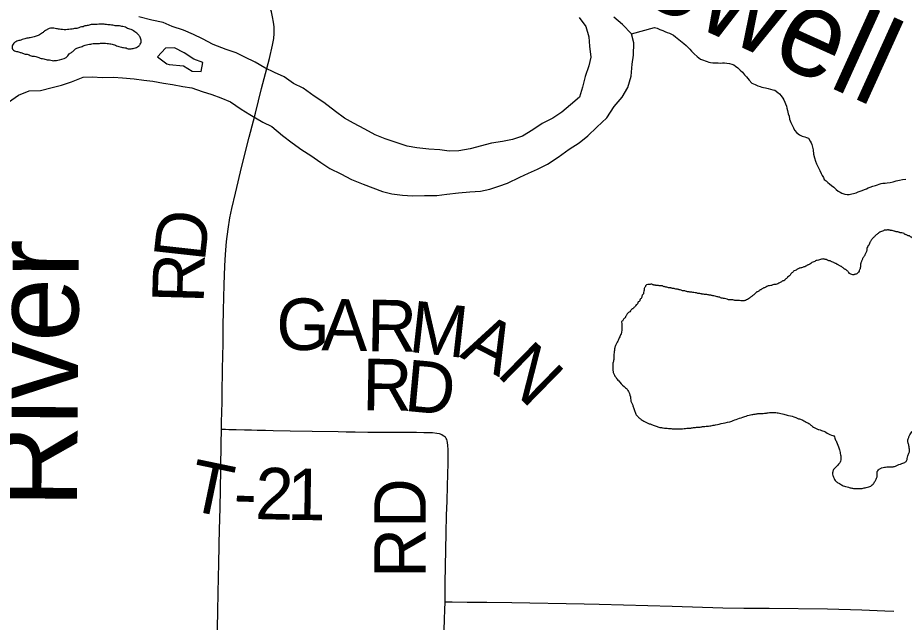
# Model space of a CAD drawing. Extents: x -483 to 680, y 0 to 440.
# Drawn here: x 240.28 to 289.15, y 248.81 to 282.12 of the extents above; entities that cross this region are included whole.
import ezdxf

# ---------------------------------------------------------------- set-up
doc = ezdxf.new("R2010")
doc.units = 0
for name, color, linetype in [('GM_X_County_Road', 7, 'Continuous'), ('GM_X_County_Road_Text', 7, 'Continuous'), ('GM_X_Major_River', 7, 'Continuous'), ('GM_X_Major_River_Text', 7, 'Continuous'), ('GM_X_Minor_Lake', 7, 'Continuous'), ('GM_X_Minor_River', 7, 'Continuous'), ('GM_X_Minor_River_Text', 7, 'Continuous'), ('GM_X_Township_Road', 7, 'Continuous'), ('GM_X_Township_Road_Text', 7, 'Continuous')]:
    doc.layers.add(name, color=color, linetype=linetype)

msp = doc.modelspace()

# ---------------------------------------------------------------- linework, layer by layer
at = {"layer": 'GM_X_County_Road'}
for points in [[(254.152, 279.874), (254.33, 280.605), (254.397, 280.979), (254.412, 281.254), (254.406, 281.623), (254.382, 281.867), (254.328, 282.168), (254.258, 282.434), (254.185, 282.635), (254.06, 282.916), (253.974, 283.098)], [(253.27, 276.434), (253.378, 276.855), (253.723, 278.21), (254.152, 279.874)], [(251.509, 259.452), (251.515, 259.825), (251.54, 260.943), (251.548, 261.378), (251.573, 262.777), (251.594, 264.168), (251.593, 264.415), (251.607, 265.097), (251.628, 265.998), (251.655, 267.396), (251.688, 268.453), (251.726, 269.075), (251.791, 269.789), (251.879, 270.469), (251.978, 271.084), (252.08, 271.604), (252.274, 272.453), (252.637, 273.933), (253.036, 275.53), (253.27, 276.434)], [(251.256, 246.808), (251.299, 249.391), (251.322, 250.452), (251.357, 252.063), (251.377, 252.993), (251.399, 254.016), (251.41, 254.388), (251.451, 256.034), (251.494, 258.613), (251.509, 259.452)]]:
    msp.add_lwpolyline(points, dxfattribs=at)
at = {"layer": 'GM_X_Major_River'}
for points in [[(239.766, 277.473), (240.326, 277.856), (240.901, 278.087), (241.527, 278.108), (242.177, 278.28), (242.692, 278.398), (243.247, 278.592), (243.88, 278.84), (244.373, 278.864), (244.941, 278.83), (245.548, 278.851), (246.059, 278.799), (246.702, 278.744), (247.23, 278.672), (247.722, 278.621), (248.306, 278.51), (248.816, 278.439), (249.382, 278.328), (249.873, 278.258), (250.436, 278.053), (250.981, 277.886), (251.469, 277.702), (252.012, 277.478), (252.589, 277.083), (253.073, 276.785), (253.782, 276.367), (254.287, 276.125), (254.88, 275.635), (255.399, 275.222), (255.938, 274.846), (256.441, 274.529), (256.98, 274.135), (257.483, 273.817), (258.081, 273.516), (258.679, 273.196), (259.317, 272.951), (259.861, 272.746), (260.386, 272.542), (260.894, 272.414), (261.48, 272.341), (262.048, 272.307), (262.693, 272.327), (263.375, 272.327), (263.927, 272.388), (264.573, 272.465), (265.201, 272.523), (265.789, 272.564), (266.304, 272.664), (266.802, 272.84), (267.28, 272.997), (267.953, 273.339), (268.433, 273.554), (268.932, 273.768), (269.49, 274.056), (270.069, 274.439), (270.669, 274.878), (271.229, 275.223), (271.713, 275.608), (272.201, 276.088), (272.746, 276.604), (273.161, 277.219), (273.593, 277.738), (273.911, 278.28), (274.1, 278.901), (274.156, 279.563), (274.227, 280.054), (274.246, 280.737), (274.108, 281.234), (273.61, 281.741), (273.129, 282.153)], [(271.233, 282.129), (271.598, 281.626), (271.753, 281.071), (271.795, 280.558), (271.873, 279.948), (271.764, 279.458), (271.559, 278.876), (271.409, 278.291), (271.243, 277.746), (270.757, 277.323), (270.272, 276.919), (269.769, 276.591), (269.192, 276.284), (268.671, 275.938), (268.111, 275.593), (267.556, 275.4), (267.003, 275.301), (266.394, 275.204), (265.21, 274.895), (264.6, 274.779), (264.069, 274.774), (263.54, 274.846), (262.935, 274.882), (262.273, 274.957), (261.745, 275.047), (261.087, 275.255), (260.524, 275.441), (259.98, 275.665), (259.402, 275.984), (258.785, 276.305), (258.281, 276.585), (257.799, 276.958), (257.149, 277.45), (256.627, 277.787), (256.015, 278.241), (255.472, 278.502), (254.97, 278.858), (254.427, 279.1), (253.904, 279.361), (253.362, 279.661), (252.802, 279.942), (252.315, 280.183), (251.771, 280.369), (251.058, 280.635), (250.46, 280.955), (249.974, 281.196), (249.412, 281.439), (248.792, 281.627), (248.286, 281.85), (247.664, 281.981), (246.949, 282.171)], [(249.414, 279.466), (249.898, 279.168), (250.391, 279.154), (250.48, 279.645), (249.993, 279.829), (249.453, 280.186), (248.911, 280.466), (248.417, 280.442), (247.987, 279.96), (248.488, 279.586), (248.62, 279.545)], [(248.62, 279.545), (249.414, 279.466)]]:
    msp.add_lwpolyline(points, dxfattribs=at)
for points in [[(242.651, 281.47), (242.518, 281.492), (242.405, 281.514), (242.273, 281.536), (242.159, 281.539), (242.007, 281.524), (241.872, 281.452), (241.757, 281.379), (241.64, 281.286), (241.525, 281.213), (241.409, 281.14), (241.18, 281.07), (241.027, 281.036), (240.912, 281.001), (240.779, 280.985), (240.664, 280.95), (240.512, 280.916), (240.397, 280.862), (240.282, 280.846), (240.167, 280.792), (240.052, 280.719), (239.992, 280.606), (239.97, 280.493), (239.986, 280.379), (240.098, 280.3), (240.211, 280.259), (240.324, 280.237), (240.493, 280.176), (240.681, 280.115), (240.908, 280.071), (241.02, 280.011), (241.134, 280.008), (241.266, 279.986), (241.379, 279.945), (241.642, 279.863), (241.775, 279.84), (241.906, 279.799), (242.02, 279.796), (242.171, 279.754), (242.285, 279.752), (242.418, 279.767), (242.57, 279.801), (243.031, 280.018), (243.11, 280.13), (243.245, 280.202), (243.381, 280.332), (243.535, 280.442), (243.65, 280.477), (243.765, 280.512), (243.88, 280.566), (243.995, 280.601), (244.3, 280.669), (244.566, 280.701), (244.718, 280.697), (244.832, 280.713), (245.211, 280.703), (245.476, 280.659), (245.608, 280.617), (245.72, 280.577), (245.852, 280.535), (246.003, 280.494), (246.116, 280.472), (246.248, 280.45), (246.361, 280.409), (246.475, 280.406), (246.703, 280.438), (246.934, 280.546), (247.031, 280.658), (247.072, 280.771), (247.075, 280.884), (247.04, 280.999), (246.949, 281.153), (246.838, 281.27), (246.726, 281.349), (246.464, 281.488), (246.333, 281.529), (246.22, 281.589), (246.07, 281.631), (245.956, 281.653), (245.824, 281.675), (245.653, 281.679), (245.521, 281.702), (245.37, 281.725), (245.237, 281.728), (245.105, 281.75), (244.972, 281.754), (244.745, 281.759), (244.574, 281.745), (244.441, 281.748), (244.213, 281.716), (244.098, 281.681), (243.984, 281.664), (243.885, 281.619)], [(243.885, 281.619), (243.716, 281.595), (243.582, 281.542), (243.468, 281.525), (243.354, 281.509), (243.011, 281.461), (242.651, 281.47)]]:
    msp.add_spline(points, degree=3, dxfattribs=at)
at = {"layer": 'GM_X_Minor_Lake'}
for points in [[(290.913, 269.044), (290.892, 269.058), (290.836, 269.117), (290.78, 269.156), (290.725, 269.214), (290.668, 269.235), (290.296, 269.528), (290.24, 269.568), (290.165, 269.608), (290.11, 269.666), (290.053, 269.686), (289.997, 269.726), (289.922, 269.765), (289.81, 269.844), (289.736, 269.884), (289.679, 269.923), (289.605, 269.963), (289.549, 270.021), (289.493, 270.042), (289.437, 270.1), (289.361, 270.102), (289.305, 270.141), (289.249, 270.161), (289.193, 270.182), (289.137, 270.221), (289.024, 270.262), (288.967, 270.263), (288.892, 270.284), (288.835, 270.304), (288.76, 270.325), (288.703, 270.327), (288.646, 270.347), (288.59, 270.348), (288.477, 270.389), (288.42, 270.391), (288.363, 270.411), (288.306, 270.412), (288.25, 270.433), (288.193, 270.415), (288.079, 270.418), (288.002, 270.382), (287.887, 270.347), (287.714, 270.237), (287.636, 270.182), (287.5, 270.052), (287.442, 269.997), (287.384, 269.941), (287.325, 269.867), (287.285, 269.792), (287.246, 269.736), (287.205, 269.623), (287.166, 269.567), (287.084, 269.341), (287.083, 269.284), (287.062, 269.228), (287.023, 269.172), (286.962, 269.003), (286.923, 268.947), (286.864, 268.872), (286.843, 268.816), (286.804, 268.741), (286.783, 268.684), (286.762, 268.609), (286.742, 268.553), (286.739, 268.439), (286.718, 268.344), (286.716, 268.287), (286.677, 268.231), (286.656, 268.156), (286.577, 268.044), (286.5, 267.989), (286.424, 267.972), (286.367, 267.954), (286.31, 267.956), (286.197, 267.996), (286.085, 268.075), (286.03, 268.152), (285.974, 268.192), (285.918, 268.25), (285.862, 268.27), (285.806, 268.31), (285.75, 268.349)], [(285.75, 268.349), (285.695, 268.407), (285.638, 268.428), (285.563, 268.467), (285.507, 268.507), (285.451, 268.527), (285.395, 268.567), (285.32, 268.587), (285.264, 268.627), (285.151, 268.667), (285.095, 268.707), (285.038, 268.727), (284.982, 268.728), (284.925, 268.749), (284.869, 268.788), (284.812, 268.79), (284.756, 268.81), (284.585, 268.814), (284.356, 268.744), (284.299, 268.745), (284.221, 268.69), (284.107, 268.655), (283.875, 268.509), (283.818, 268.491), (283.76, 268.455), (283.664, 268.4), (283.607, 268.383), (283.53, 268.346), (283.358, 268.313), (283.3, 268.276), (283.243, 268.259), (283.185, 268.203), (283.07, 268.168), (283.031, 268.112), (282.953, 268.057), (282.895, 268.001), (282.816, 267.889), (282.72, 267.835), (282.7, 267.778), (282.622, 267.723), (282.563, 267.649), (282.449, 267.614), (282.314, 267.522), (282.237, 267.486), (282.007, 267.416), (281.951, 267.417), (281.874, 267.381), (281.797, 267.364), (281.511, 267.276), (281.453, 267.239), (281.376, 267.222), (281.319, 267.186), (281.241, 267.131), (281.184, 267.113), (281.126, 267.058), (281.049, 267.022), (280.991, 266.985), (280.913, 266.911), (280.855, 266.855), (280.797, 266.819), (280.739, 266.763), (280.681, 266.727), (280.622, 266.671), (280.507, 266.598), (280.392, 266.544), (280.315, 266.527), (279.974, 266.535), (279.803, 266.54), (279.747, 266.56), (279.538, 266.565), (279.237, 266.648), (279.18, 266.65), (279.066, 266.671), (278.973, 266.712), (278.784, 266.754), (278.652, 266.795), (278.595, 266.797), (278.52, 266.818), (278.35, 266.841), (278.274, 266.862), (278.198, 266.863), (278.085, 266.885), (277.99, 266.888), (277.934, 266.908), (277.82, 266.93), (277.763, 266.931), (277.688, 266.952), (277.556, 266.974), (277.499, 266.976), (277.386, 266.997), (277.329, 266.999), (277.253, 267.02), (277.196, 267.021), (277.14, 267.041), (277.046, 267.063), (276.951, 267.065), (276.894, 267.085)], [(276.894, 267.085), (276.801, 267.126), (276.744, 267.127), (276.687, 267.147), (276.612, 267.168), (276.555, 267.17), (276.461, 267.191), (276.404, 267.192), (276.328, 267.213), (276.272, 267.233), (276.215, 267.235), (276.158, 267.236), (276.064, 267.276), (276.007, 267.278), (275.932, 267.299), (275.875, 267.3), (275.819, 267.339), (275.629, 267.344), (275.573, 267.364), (275.459, 267.367), (275.403, 267.387), (275.346, 267.389), (275.29, 267.409), (275.233, 267.43), (275.176, 267.431), (275.119, 267.413), (275.005, 267.416), (274.889, 267.343), (274.869, 267.287), (274.83, 267.231), (274.809, 267.174), (274.807, 267.098), (274.767, 266.986), (274.765, 266.91), (274.706, 266.835), (274.685, 266.779), (274.684, 266.722), (274.644, 266.647), (274.586, 266.61), (274.565, 266.516), (274.488, 266.461), (274.447, 266.348), (274.37, 266.293), (274.311, 266.199), (274.233, 266.144), (274.213, 266.088), (274.155, 266.07), (274.058, 265.959), (273.98, 265.885), (273.922, 265.848), (273.844, 265.736), (273.785, 265.662), (273.764, 265.586), (273.687, 265.531), (273.647, 265.475), (273.607, 265.401), (273.568, 265.388)], [(273.568, 265.388), (273.552, 264.769), (273.51, 264.637), (273.41, 264.431), (273.329, 264.243), (273.249, 264.093), (273.187, 263.924), (273.163, 263.735), (273.135, 263.412), (273.132, 263.279), (273.089, 263.09), (273.081, 262.768), (273.095, 262.615), (273.149, 262.462), (273.258, 262.288), (273.405, 262.113), (273.701, 261.801), (273.869, 261.644), (273.959, 261.49), (274.065, 261.145), (274.079, 260.992), (274.152, 260.838), (274.205, 260.685), (274.275, 260.474), (274.346, 260.282), (274.475, 260.127), (274.605, 260.009), (274.792, 259.89), (274.942, 259.81), (275.093, 259.749), (275.262, 259.688), (275.469, 259.606), (275.677, 259.543), (275.866, 259.519), (275.999, 259.497), (276.151, 259.493), (276.359, 259.468), (276.644, 259.46), (276.93, 259.472), (277.235, 259.502), (277.426, 259.516), (277.636, 259.548), (277.902, 259.56), (278.074, 259.593), (278.227, 259.608), (278.494, 259.639), (278.742, 259.689), (279.163, 259.773), (279.642, 259.893), (279.968, 260.018), (280.352, 260.14), (280.678, 260.246), (280.926, 260.277), (281.136, 260.309), (281.441, 260.32), (281.651, 260.353), (281.803, 260.368), (282.069, 260.36), (282.202, 260.338), (282.353, 260.315), (282.504, 260.273), (282.769, 260.209), (283.165, 260.084), (283.315, 260.023), (283.523, 259.96), (283.692, 259.861), (283.879, 259.761), (284.028, 259.643), (284.29, 259.484), (284.441, 259.423), (284.592, 259.381), (284.817, 259.28), (285.136, 259.119), (285.268, 259.077), (285.322, 258.943), (285.412, 258.751), (285.554, 258.367), (285.623, 258.099), (285.654, 257.851), (285.631, 257.681), (285.531, 257.512), (285.257, 257.216), (285.196, 257.046), (285.211, 256.894), (285.282, 256.721), (285.411, 256.546), (285.579, 256.447), (285.785, 256.327), (285.917, 256.286), (286.068, 256.244), (286.257, 256.201), (286.447, 256.176), (286.618, 256.172), (286.827, 256.185), (287.057, 256.236), (287.306, 256.306), (287.462, 256.453)], [(287.462, 256.453), (287.562, 256.622), (287.622, 256.753), (287.664, 256.885), (287.649, 257.056), (287.768, 257.243), (287.903, 257.316), (288.056, 257.35), (288.19, 257.365), (288.399, 257.378), (288.532, 257.375), (288.705, 257.427), (289.012, 257.552), (289.224, 257.641), (289.304, 257.772), (289.326, 257.905), (289.368, 258.037), (289.429, 258.206), (289.433, 258.339), (289.417, 258.472), (289.366, 258.683), (289.351, 258.854), (289.393, 258.986), (289.454, 259.136), (289.611, 259.341), (289.921, 259.561), (290.094, 259.613), (290.231, 259.762), (290.273, 259.913), (290.314, 260.045), (290.338, 260.215), (290.4, 260.403), (290.442, 260.535), (290.502, 260.667), (290.622, 260.872), (290.721, 261.022), (290.801, 261.172), (290.88, 261.303), (290.923, 261.473), (291.006, 261.736), (291.067, 261.887), (291.454, 262.542)]]:
    msp.add_spline(points, degree=3, dxfattribs=at)
at = {"layer": 'GM_X_Minor_River'}
for points in [[(274.108, 281.234), (275.379, 281.575), (275.53, 281.533), (275.68, 281.472), (275.831, 281.411), (275.943, 281.351), (276.075, 281.31), (276.207, 281.269), (276.32, 281.209), (276.432, 281.149), (276.544, 281.07), (276.991, 280.698), (277.121, 280.581), (277.232, 280.483), (277.325, 280.386), (277.417, 280.27), (277.565, 280.133), (277.732, 279.977), (277.919, 279.839), (278.088, 279.778), (278.182, 279.737), (278.276, 279.697), (278.37, 279.676), (278.465, 279.654), (278.597, 279.632), (278.749, 279.628), (278.882, 279.625), (278.996, 279.622), (279.129, 279.637), (279.243, 279.635), (279.376, 279.612), (279.508, 279.59), (279.64, 279.567), (279.753, 279.527), (279.846, 279.448), (279.977, 279.35), (280.107, 279.233), (280.237, 279.116), (280.347, 278.98), (280.458, 278.863), (280.532, 278.766), (280.606, 278.67), (280.754, 278.514), (280.922, 278.434), (281.073, 278.373), (281.205, 278.331), (281.299, 278.291), (281.393, 278.27), (281.507, 278.248), (281.639, 278.226), (281.771, 278.184), (281.903, 278.143), (282.016, 278.121), (282.184, 278.003), (282.277, 277.925), (282.369, 277.808), (282.461, 277.692), (282.516, 277.596), (282.659, 277.25), (282.675, 277.136), (282.71, 277.002), (282.744, 276.83), (282.797, 276.696), (282.831, 276.524), (282.903, 276.351), (282.975, 276.198), (283.047, 276.044), (283.101, 275.929), (283.23, 275.773), (283.379, 275.656), (283.529, 275.595), (283.661, 275.554), (283.755, 275.513), (283.868, 275.472), (283.959, 275.318), (284.014, 275.222), (284.049, 275.126), (284.084, 274.992), (284.118, 274.839), (284.15, 274.592), (284.202, 274.4), (284.254, 274.209), (284.308, 274.075), (284.362, 273.959), (284.416, 273.844), (284.488, 273.691), (284.56, 273.537), (284.615, 273.421), (284.688, 273.306), (284.742, 273.209), (284.835, 273.131), (284.928, 273.034), (285.021, 272.974), (285.133, 272.877), (285.263, 272.778), (285.393, 272.661), (285.505, 272.563), (285.617, 272.503), (285.711, 272.444)], [(285.711, 272.444), (285.881, 272.402), (285.994, 272.38), (286.108, 272.377), (286.49, 272.462), (286.605, 272.516), (286.72, 272.552), (286.835, 272.606), (286.951, 272.66), (287.065, 272.695), (287.162, 272.749), (287.277, 272.784), (287.411, 272.838), (287.564, 272.872), (287.679, 272.907), (287.774, 272.943), (287.87, 272.978), (287.966, 272.995), (288.099, 273.01), (288.213, 273.026), (288.366, 273.042), (288.538, 273.075), (288.71, 273.128), (288.882, 273.161), (289.053, 273.195), (289.244, 273.228)]]:
    msp.add_lwpolyline(points, dxfattribs=at)
at = {"layer": 'GM_X_Township_Road'}
for points in [[(251.509, 259.452), (251.738, 259.441), (251.919, 259.432), (252.321, 259.423), (252.786, 259.413), (253.159, 259.404), (253.47, 259.396), (253.749, 259.384), (253.933, 259.383), (254.363, 259.379), (255.298, 259.363), (256.507, 259.341), (257.932, 259.318), (258.388, 259.306), (258.882, 259.295), (259.568, 259.289), (259.88, 259.286), (260.736, 259.282), (261.555, 259.275), (261.708, 259.274), (261.831, 259.274), (261.954, 259.277), (262.26, 259.278), (262.668, 259.268), (263.141, 259.256), (263.387, 259.231), (263.508, 259.201), (263.651, 259.146), (263.728, 259.101), (263.769, 259.077), (263.818, 259.04), (263.861, 259.007)], [(263.832, 249.928), (263.833, 250.961), (263.871, 252.814), (263.893, 253.725), (263.916, 254.708), (263.947, 255.484), (263.972, 256.325), (264.009, 257.566), (263.999, 258.331), (263.986, 258.544), (263.969, 258.709), (263.95, 258.81), (263.932, 258.875), (263.904, 258.94), (263.861, 259.007)], [(263.416, 224.912), (263.42, 225.302), (263.43, 226.235), (263.439, 227.074), (263.465, 228.908), (263.49, 231.612), (263.506, 233.136), (263.516, 234.068), (263.53, 234.783), (263.54, 235.311), (263.547, 235.498), (263.564, 237.239), (263.573, 237.549), (263.603, 239.009), (263.632, 240.532), (263.677, 242.924), (263.695, 243.947), (263.7, 244.563), (263.732, 246.175), (263.751, 247.104), (263.769, 247.721), (263.805, 248.994), (263.823, 249.474), (263.832, 249.928)], [(263.832, 249.928), (264.219, 249.932), (265.06, 249.924), (266.135, 249.908), (267.509, 249.888), (271.506, 249.818), (272.321, 249.807), (276.35, 249.689), (279.14, 249.607), (280.306, 249.588), (281.696, 249.579), (284.92, 249.549), (286.812, 249.485), (288.076, 249.443), (288.572, 249.425)]]:
    msp.add_lwpolyline(points, dxfattribs=at)

# ---------------------------------------------------------------- texts
at = {"layer": 'GM_X_County_Road_Text'}
for s, rotation, p in [('D', 83.6797, (250.583, 268.63)), ('R', 88.425, (250.523, 266.359))]:
    msp.add_text(s, height=2.841, rotation=rotation, dxfattribs=at).set_placement(p)
at = {"layer": 'GM_X_Major_River_Text'}
msp.add_text('River', height=4.7379, rotation=89.6069, dxfattribs=at).set_placement((243.544, 255.095))
at = {"layer": 'GM_X_Minor_River_Text'}
msp.add_text('Powell', height=4.7373, rotation=335.6205, dxfattribs=at).set_placement((270.436, 284.896))
at = {"layer": 'GM_X_Township_Road_Text'}
for s, height, rotation, p in [('G', 2.841, 359.0747, (254.511, 263.831)), ('A', 2.841, 359.071, (257.011, 263.791)), ('R', 2.841, 359.0554, (259.51, 263.75)), ('M', 2.841, 353.604, (261.772, 263.717)), ('A', 2.841, 333.0236, (264.579, 263.45)), ('N', 2.841, 315.6195, (266.622, 262.449)), ('R', 2.841, 359.0749, (259.256, 260.497)), ('D', 2.841, 354.6959, (261.532, 260.463)), ('T', 2.841, 348.2303, (249.535, 255.031)), ('2', 2.841, 358.645, (253.34, 254.497)), ('1', 2.841, 359.1143, (255.115, 254.455)), ('RD', 2.8409, 90, (262.773, 251.255)), ('-', 2.841, 358.2209, (252.151, 254.534))]:
    msp.add_text(s, height=height, rotation=rotation, dxfattribs=at).set_placement(p)

doc.saveas('drawing.dxf')
